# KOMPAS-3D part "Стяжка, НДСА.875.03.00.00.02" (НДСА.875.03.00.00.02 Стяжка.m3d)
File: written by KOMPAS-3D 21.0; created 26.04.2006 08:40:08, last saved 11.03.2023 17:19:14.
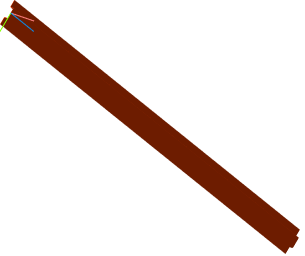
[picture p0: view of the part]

Document properties: Автор: Туленинова Л.Е.; Организация: Эсто-вакуум; Полное имя файла: C:\Users\s.pischagina\Desktop\PLM\НДСА.875.03.00.00.02 Стяжка.m3d

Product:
- Part/product: Стяжка  | designation НДСА.875.03.00.00.02
    Масса: 0.4226
    additional columns: <item xmlns="http://appius.ru/pdm" xmlns:xs="http://www.w3.org/2001/XMLSchema" x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; <item xmlns="http://appius.ru/pdm" xmlns:xs="http://www.w3.org/2001/XMLSchema" x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; <item xmlns="http://appius.ru/pdm" xmlns:xs="http://www.w3.org/2001/XMLSchema" x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; <item xmlns="http://appius.ru/pdm" xmlns:xs="http://www.w3.org/2001/XMLSchema" x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; <item xmlns="http://appius.ru/pdm" xmlns:xs="http://www.w3.org/2001/XMLSchema" x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; <item xmlns="http://appius.ru/pdm" xmlns:xs="http://www.w3.org/2001/XMLSchema" x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; <item xmlns="http://appius.ru/pdm" xmlns:xs="http://www.w3.org/2001/XMLSchema" x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; <item xmlns="http://appius.ru/pdm" xmlns:xs="http://www.w3.org/2001/XMLSchema" x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
    source file: НДСА.875.03.00.00.02 Стяжка.cdw

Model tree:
1. Плоскость XY
2. Плоскость ZX
3. Плоскость ZY
4. Начало координат
5. Эскиз:1
6. Листовое тело:1
     Расстояние 1 = 826; Радиус сгиба = 1; Коэффициент = 0.4; Величина сгиба = 10; Радиус сгиба = 1; Коэффициент = 0.4; Величина сгиба = 10; Радиус сгиба = 1; Коэффициент = 0.4; Величина сгиба = 10; Радиус сгиба = 1; Коэффициент = 0.4; Величина сгиба = 10
7. Развертка  (labels: Листовое тело:1; Листовое тело:1)

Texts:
  НДСА.875.03.00.00.02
